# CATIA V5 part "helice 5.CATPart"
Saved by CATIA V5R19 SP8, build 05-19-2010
Part number: helice 5
Bounding box of the stored display mesh (mm): x -17.46 to 17.321, y -30 to 195, z -10.242 to 20
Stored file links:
  G:\EU_thinkMotion\CFAO_2010\MMS_groupe2\MMS_groupe2\A reprendre\splanchenault\Planchenault\helice 5.CATPart
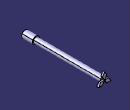
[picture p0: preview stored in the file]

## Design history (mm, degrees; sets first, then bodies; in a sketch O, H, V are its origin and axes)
Body1 (main body)
  Sketch1 on xy-plane, origin (0, 0, 0), H (1, 0, 0), V (0, 1, 0)
    line L1 (0, 0) -> (0, -30)
    line L2 (0, -30) -> (10, -30)
    line L3 (10, -30) -> (10, 0)
    point P3 (10, 0)
    line L4 (10, 0) -> (7.5, 0)
    line L5 (7.5, 190) -> (7.5, 0)
    line L6 (7.5, 190) -> (0, 190)
    line L7 (0, 190) -> (0, 0)
    length L6 = 7.5
    length L2 = 10
    length L7 = 190
    length L3 = 30
    vertical: L1 V, L3 V, L5 V, L7 V
    horizontal: L2 H, L4 H, L6 H
    coincidence: P3 H
  Shaft1: profile Sketch1, axis Sketch1.L7, angle 360
  Sketch2 on face of Shaft1 from Sketch1.L6, origin (0, 190, 0), H (-1, 0, 0), V (0, 0, 1)
    construction line L1 (19.3649, -11.1803) -> (-19.3649, 11.1803)
    axis line L2 (-18.8109, -11.0218) -> (19.4278, 11.0553)
    line L3 (0, 0) -> (5.7735, 10)
    point P5 (5.7735, 10)
    line L4 (5.7735, 10) -> (0, 20)
    point P6 (0, 20)
    line L5 (0, 20) -> (-5.7735, 10)
    point P7 (-5.7735, 10)
    line L6 (-5.7735, 10) -> (0, 0)
    point P8 (-11.547, 0)
    point P9 (-17.3205, -10)
    line L7 (-17.3205, -10) -> (-11.547, 0)
    point P10 (-5.7735, -10)
    line L8 (-5.7735, -10) -> (-17.3205, -10)
    point P11 (0, 0)
    line L9 (-11.547, 0) -> (0, 0)
    line L10 (0, 0) -> (-5.7735, -10)
    point P12 (0.1397, -0.242)
    point P13 (5.9132, -10.242)
    line L11 (5.9132, -10.242) -> (0.1397, -0.242)
    point P14 (17.4602, -10.242)
    line L12 (17.4602, -10.242) -> (5.9132, -10.242)
    point P15 (11.6867, -0.242)
    line L13 (11.6867, -0.242) -> (17.4602, -10.242)
    line L14 (0.1397, -0.242) -> (11.6867, -0.242)
    perpendicularity: L3 L1, L4 L2
    coincidence: P6 V, O P11
    parallelism: L5 L3, L6 L4
    symmetry: P7 P8 L1, P6 P9 L1, L5 L7 L1, P5 P10 L1, L4 L8 L1, O P11 L1, L6 L9 L1, L3 L10 L1, O P12 L2, P7 P13 L2, L6 L11 L2, P6 P14 L2, L5 L12 L2, P5 P15 L2, L4 L13 L2, L3 L14 L2
  Pad1: profile Sketch2, direction (0, 1, 0), length 5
